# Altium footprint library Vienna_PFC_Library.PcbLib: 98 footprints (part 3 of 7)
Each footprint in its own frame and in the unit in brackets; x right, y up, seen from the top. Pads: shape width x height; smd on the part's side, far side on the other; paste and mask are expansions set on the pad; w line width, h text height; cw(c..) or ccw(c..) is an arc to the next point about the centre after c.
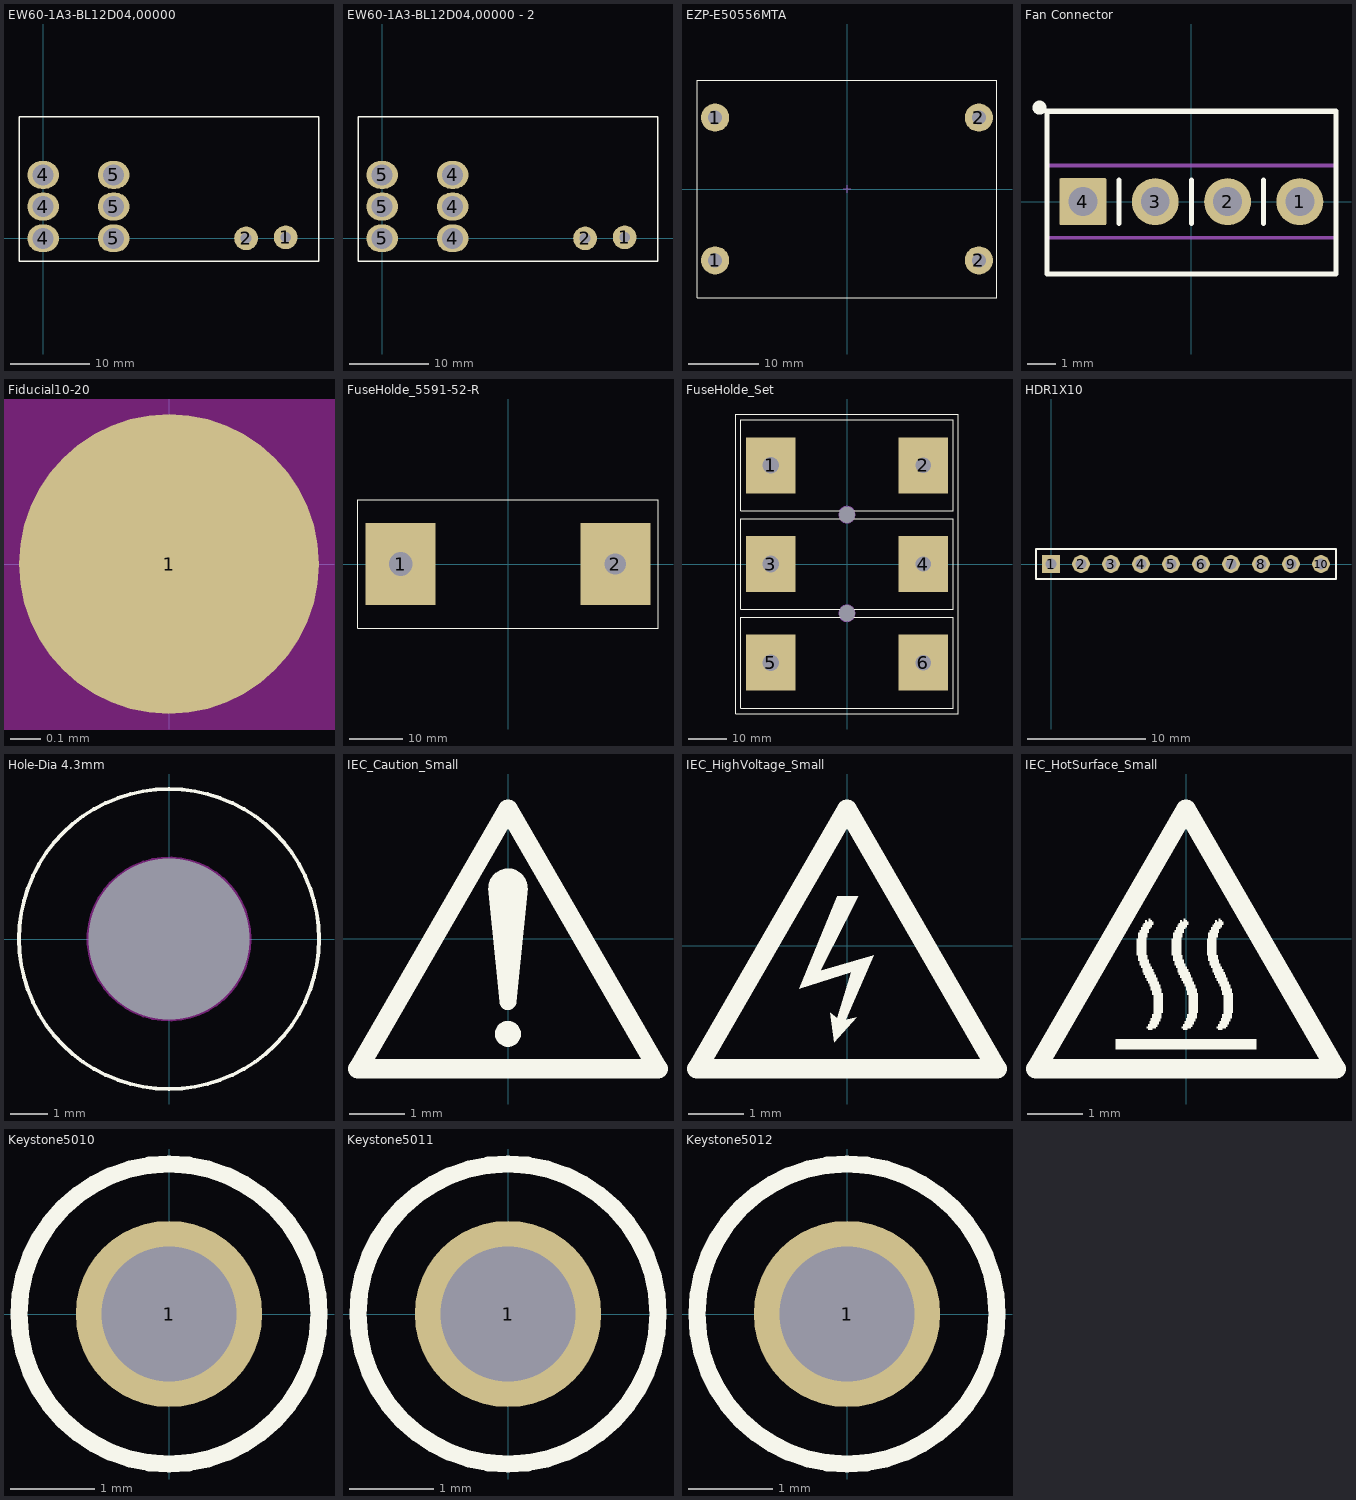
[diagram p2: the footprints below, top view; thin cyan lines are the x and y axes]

## EW60-1A3-BL12D04,00000 [mm] "Capacitor"
pads (8):
  round 3 hole 1.35: 1(30.6,0.128) 2(25.6,0)
  oval 4x3.5 hole 2.65: 4(0,0) 4(0,4) 4(0,8) 5(8.9,0) 5(8.9,4) 5(8.9,8)
Top Overlay:
  lines w0.178: -3.048,-2.922 34.798,-2.922 34.798,15.366 -3.048,15.366 -3.048,-2.922
Mechanical 15:
  lines w0.1: -0.5,8 0.5,8 ; 0,7.5 0,8.5
3D body "EW60-1A3-BL12D04,00000.stp": height 30.4, standoff -4, extent -2.51,-2.378 34.29,14.822

## EW60-1A3-BL12D04,00000 - 2 [mm] "Capacitor"
pads (8):
  round 3 hole 1.35: 1(30.6,0.128) 2(25.6,0)
  oval 4x3.5 hole 2.65: 4(8.9,0) 4(8.9,4) 4(8.9,8) 5(0,0) 5(0,4) 5(0,8)
Top Overlay:
  lines w0.178: -3.048,-2.922 34.798,-2.922 34.798,15.366 -3.048,15.366 -3.048,-2.922
Mechanical 15:
  lines w0.1: -0.5,8 0.5,8 ; 0,7.5 0,8.5
3D body "EW60-1A3-BL12D04,00000.stp": height 30.4, standoff -4, extent -2.51,-2.378 34.29,14.822

## EZP-E50556MTA [mm] "Capacitor"
height 17
pads (4):
  round 4 hole 2: 1(-18.75,-10.15) 1(-18.75,10.15) 2(18.75,-10.15) 2(18.75,10.15)
Top Overlay:
  lines w0.178: -21.336,-15.494 -21.336,15.494 21.336,15.494 21.336,-15.494 -21.336,-15.494
Mechanical 15:
  lines w0.1: -0.5,0 0.5,0 ; 0,-0.5 0,0.5
3D body "FilmCap.STEP": height 51.5, standoff -4, extent -20.774,-15.007 20.726,14.993

## Fan Connector [mm]
height 8.382
pads (4):
  round 1.65 hole 1.016: 1(3.81,0) 2(1.27,0) 3(-1.27,0)
  rrect6% 1.65x1.65 hole 1.016: 4(-3.81,0)
Top Overlay:
  circle w0.25: c-5.334,3.302 r0.125
  lines w0.178: -2.54,-2.54 2.54,-2.54 ; -2.54,-0.762 -2.54,0.762 ; -2.54,3.175 2.54,3.175 ; 0,-0.762 0,0.762 ; 2.54,-0.762 2.54,0.762 ; -5.08,-2.54 5.08,-2.54 5.08,-1.27 5.08,3.175 0,3.175 -5.08,3.175 -5.08,-2.54
Mechanical 5:
  lines w0.127: -5.08,-1.27 5.08,-1.27 5.08,1.27 -5.08,1.27 -5.08,-1.27
3D body: height 8.38, standoff -2.03, extent 0.953,-0.317 1.587,0.317
3D body: height 8.38, standoff -2.03, extent -1.587,-0.317 -0.953,0.317
3D body: height 2.54, standoff 0, extent 0.001,-1.269 5.08,1.27
3D body: height 2.54, standoff 0, extent -5.079,-1.269 -0.001,1.269
3D body: height 8, standoff 0, extent -4.064,1.27 4.064,3.048

## Fiducial10-20 [mm]
pads (1):
  round 1 smd mask+0.5: 1(0,0)
Top Layer keep-out:
  circle w1.178: c0,0 r0.5

## FuseHolde_5591-52-R [mm]
height 22.6
pads (2):
  rect 13x15.3 hole 4.4: 1(-20,0)
  rect 13x15.3 hole 4: 2(20,0)
Top Overlay:
  lines w0.2: -27.94,-11.938 27.94,-11.938 27.94,11.938 -27.94,11.938 -27.94,-11.938
3D body: height 12, standoff 0, extent -23.368,-4.447 -16.868,4.447
3D body: height 12, standoff 0, extent 16.614,-4.447 23.114,4.447

## FuseHolde_Set [mm]
height 22.6
pads (8):
  round 0 hole 4.3: 0(0,-12.945) 0(0,12.954)
  rect 13x14.7 hole 4.4: 1(-20,25.908) 3(-20,0) 5(-20,-25.908)
  rect 13x14.7 hole 4: 2(20,25.908) 4(20,0) 6(20,-25.908)
Top Overlay:
  lines w0.2: -29.21,-39.37 -29.21,39.37 29.21,39.37 29.21,-39.37 -29.21,-39.37 ; -27.94,-37.846 27.94,-37.846 27.94,-13.97 -27.94,-13.97 -27.94,-37.846 ; -27.94,-11.938 -27.94,11.938 27.94,11.938 27.94,-11.938 -27.94,-11.938 ; -27.94,13.97 27.94,13.97 27.94,37.846 -27.94,37.846 -27.94,13.97
Mechanical 1:
  circle w0.013: c0,12.954 r2.15
  circle w0.013: c0,-12.945 r2.15
3D body: height 12, standoff 0, extent 16.614,-4.447 23.114,4.447
3D body: height 12, standoff 0, extent -23.368,-4.447 -16.868,4.447
3D body: height 12, standoff 0, extent -23.368,21.461 -16.868,30.355
3D body: height 12, standoff 0, extent 16.614,21.461 23.114,30.355
3D body: height 12, standoff 0, extent -23.368,-30.355 -16.868,-21.461
3D body: height 12, standoff 0, extent 16.614,-30.355 23.114,-21.461
3D body "User Library-51x14mm_fuse.STEP": height 19, standoff 5, extent -25.396,18.908 25.604,32.908
3D body "User Library-51x14mm_fuse.STEP": height 19, standoff 5, extent -25.65,-7 25.35,7
3D body "User Library-51x14mm_fuse.STEP": height 19, standoff 5, extent -25.396,-32.908 25.604,-18.908
3D body "M4_Screws.STEP": height 3.78, standoff -14.72, extent -4.602,8.45 4.398,17.45
3D body "M4_Screws.STEP": height 3.78, standoff -14.72, extent -4.424,-17.484 4.576,-8.484

## HDR1X10 [mm] "Connector; Header; 10 Position"
pads (10):
  rect 1.5x1.5 hole 0.9: 1(0,0)
  round 1.5 hole 0.9: 2(2.54,0) 3(5.08,0) 4(7.62,0) 5(10.16,0) 6(12.7,0) 7(15.24,0) 8(17.78,0) 9(20.32,0) 10(22.86,0)
Top Overlay:
  lines w0.2: -1.27,-1.27 -1.27,1.27 0.635,1.27 24.13,1.27 24.13,-1.27 -1.27,-1.27

## Heatsink [mm] "Heatsink"
Mechanical 13:
  drawing of 1722 lines, arcs and shapes, not listed
3D body "3D_Heatsink_Model.STEP": height 60.18, standoff -3.15, extent 117.272,-129.155 356.032,45.872

## Hole-Dia 4.3mm [mm] "Hole-Dia 4.3mm"
height 1
pads (1):
  round 0 hole 4.3: 0(0,0)
Top Overlay:
  circle w0.1: c0,0 r4
Keep-Out Layer:
  circle w0.1: c0,0 r2.15

## IEC_Caution_Small [mm]
Top Overlay:
  circle w0.254: c0,-1.727 r0.108
  circle w0.356: c0,0.914 r0.178
  circle w0.254: c0,-1.143 r0.025
  region: -0.356,0.914 0.356,0.914 0.152,-1.143 -0.152,-1.143
  lines w0.356: -2.718,-2.362 0,2.345 2.718,-2.362 -2.718,-2.362

## IEC_HighVoltage_Small [mm]
Top Overlay:
  region: -0.178,0.889 0.203,0.889 -0.483,-0.457 0.483,-0.178 -0.025,-1.346 0.178,-1.295 -0.229,-1.753 -0.305,-1.219 -0.178,-1.321 0.076,-0.483 -0.864,-0.787
  lines w0.356: -2.718,-2.235 2.718,-2.235 0,2.472 -2.718,-2.235

## IEC_HotSurface_Small [mm]
height 25.4
Top Overlay:
  drawing of 10 lines, arcs and shapes, not listed

## Keystone5010 [mil] "Keystone Multipurpose loops"
height 320
pads (1):
  round 87 hole 63: 1(0,0)
Top Overlay:
  circle w7.99: c0,0 r70
Mechanical 5:
  circle w5: c0,0 r69.46
3D body "Keystone_5010.stp": height 318.9, standoff -125.98, extent -63,-63.5 62.74,62.49

## Keystone5011 [mil] "Keystone Multipurpose loops"
height 320
pads (1):
  round 87 hole 63: 1(0,0)
Top Overlay:
  circle w7.99: c0,0 r70
Mechanical 5:
  circle w5: c0,0 r69.46
3D body "Keystone_5011.stp": height 318.9, standoff -125.98, extent -63,-63.5 62.74,62.49

## Keystone5012 [mil] "Keystone Multipurpose loops"
height 320
pads (1):
  round 87 hole 63: 1(0,0)
Top Overlay:
  circle w7.99: c0,0 r70
Mechanical 5:
  circle w5: c0,0 r69.46
3D body "Keystone_5012.stp": height 318.9, standoff -125.98, extent -63,-63.5 62.74,62.49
